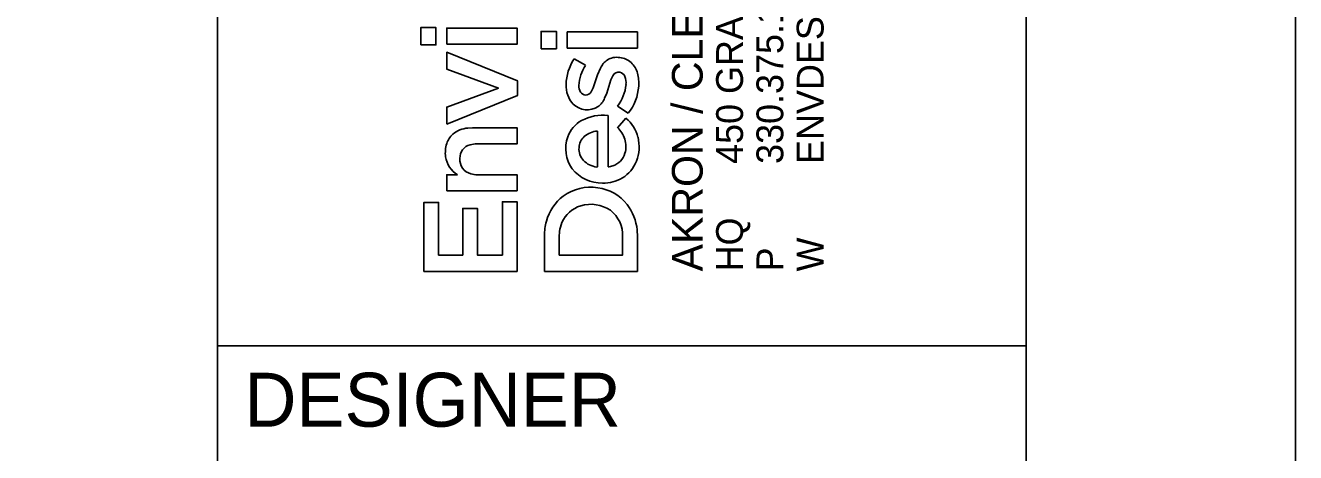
# Model space of a CAD drawing. Extents: x -0.2 to 34, y 0 to 22.
# Drawn here: x 31.644 to 34, y 2.302 to 3.094 of the extents above; entities that cross this region are included whole.
import ezdxf

# ---------------------------------------------------------------- set-up
doc = ezdxf.new("R2010")
doc.units = 0
for name, color, linetype in [('SH_Border', 7, 'Continuous'), ('SH_Cut_Line', 7, 'Continuous'), ('SH_Data', 7, 'Continuous')]:
    doc.layers.add(name, color=color, linetype=linetype)

msp = doc.modelspace()

# ---------------------------------------------------------------- linework, layer by layer
at = {"layer": 'SH_Border'}
for p, q in [((32, 0.5), (32, 21.5)), ((32, 2.5), (33.5, 2.5))]:
    msp.add_line(p, q, dxfattribs=at)
msp.add_lwpolyline([(1.5, 21.5), (33.5, 21.5), (33.5, 0.5), (1.5, 0.5)], close=True, dxfattribs=at)
at = {"layer": 'SH_Cut_Line'}
msp.add_lwpolyline([(0, 0), (34, 0), (34, 22), (0, 22)], close=True, dxfattribs=at)
at = {"layer": 'SH_Data'}
for p, q in [((32.3771, 3.0582), (32.3771, 3.0903)), ((32.3771, 3.0903), (32.4054, 3.0903)), ((32.4054, 3.0903), (32.4054, 3.0582)), ((32.4254, 3.0594), (32.4254, 3.0893)), ((32.4254, 3.0893), (32.5557, 3.0893)), ((32.5557, 3.0893), (32.5557, 3.0594)), ((32.6005, 3.0511), (32.6005, 3.0832)), ((32.6005, 3.0832), (32.6289, 3.0832)), ((32.6289, 3.0832), (32.6289, 3.0511)), ((32.6489, 3.0523), (32.6489, 3.0822)), ((32.6489, 3.0822), (32.7792, 3.0822)), ((32.7792, 3.0822), (32.7792, 3.0523)), ((32.4054, 3.0582), (32.3771, 3.0582)), ((32.5557, 3.0594), (32.4254, 3.0594)), ((32.4254, 3.0133), (32.4254, 3.0446)), ((32.4254, 3.0446), (32.5567, 2.9913)), ((32.6289, 3.0511), (32.6005, 3.0511)), ((32.7792, 3.0523), (32.6489, 3.0523)), ((32.6615, 3.0321), (32.6827, 3.0203)), ((32.5212, 2.978), (32.4254, 3.0133)), ((32.6967, 2.9787), (32.7048, 3.0026)), ((32.7048, 3.0026), (32.7104, 3.0153)), ((32.7298, 2.9933), (32.7221, 2.9688)), ((32.7334, 3.001), (32.7298, 2.9933)), ((32.4254, 2.9429), (32.5212, 2.978)), ((32.5567, 2.9913), (32.5567, 2.9644)), ((32.693, 2.9712), (32.6967, 2.9787)), ((32.5567, 2.9644), (32.4254, 2.9109)), ((32.7221, 2.9688), (32.7182, 2.9592)), ((32.4254, 2.9109), (32.4254, 2.9429)), ((32.7245, 2.9275), (32.7246, 2.8319)), ((32.7621, 2.9314), (32.742, 2.9447)), ((32.7423, 2.9046), (32.7577, 2.922)), ((32.4644, 2.904), (32.4729, 2.9044)), ((32.4729, 2.9044), (32.5557, 2.9044)), ((32.5557, 2.9044), (32.5557, 2.8746)), ((32.7049, 2.8318), (32.7049, 2.8983)), ((32.5557, 2.8746), (32.4814, 2.8746)), ((32.7036, 2.8317), (32.7049, 2.8318)), ((32.4254, 2.7875), (32.4254, 2.8173)), ((32.4254, 2.8173), (32.4455, 2.8173)), ((32.4822, 2.8173), (32.5557, 2.8173)), ((32.5557, 2.8173), (32.5557, 2.7876)), ((32.5557, 2.7876), (32.4254, 2.7875)), ((32.383, 2.6379), (32.383, 2.766)), ((32.383, 2.766), (32.4101, 2.766)), ((32.4101, 2.766), (32.4101, 2.6683)), ((32.5286, 2.6683), (32.5286, 2.7672)), ((32.5286, 2.7672), (32.5557, 2.7672)), ((32.5557, 2.7672), (32.5557, 2.6379)), ((32.455, 2.6683), (32.455, 2.7549)), ((32.455, 2.7549), (32.4822, 2.7549)), ((32.4822, 2.7549), (32.4822, 2.6683)), ((32.6347, 2.7118), (32.6341, 2.7023)), ((32.7785, 2.715), (32.7792, 2.7021)), ((32.6064, 2.638), (32.6064, 2.704)), ((32.6341, 2.7023), (32.6341, 2.6684)), ((32.7515, 2.6683), (32.7515, 2.7024)), ((32.7792, 2.7021), (32.7792, 2.638)), ((32.4101, 2.6683), (32.455, 2.6683)), ((32.4822, 2.6683), (32.5286, 2.6683)), ((32.6341, 2.6684), (32.7515, 2.6683)), ((32.5557, 2.6379), (32.383, 2.6379)), ((32.7792, 2.638), (32.6064, 2.638))]:
    msp.add_line(p, q, dxfattribs=at)
for points in [[(32.3771, 3.0582), (32.3771, 3.0903), (32.4054, 3.0903), (32.4054, 3.0582)], [(32.4254, 3.0594), (32.4254, 3.0893), (32.5557, 3.0893), (32.5557, 3.0594)], [(32.6005, 3.0511), (32.6005, 3.0832), (32.6289, 3.0832), (32.6289, 3.0511)], [(32.6489, 3.0523), (32.6489, 3.0822), (32.7792, 3.0822), (32.7792, 3.0523)], [(32.4254, 2.9109), (32.4254, 2.9429), (32.5212, 2.978), (32.4254, 3.0133), (32.4254, 3.0446), (32.5567, 2.9913), (32.5567, 2.9644)], [(32.383, 2.6379), (32.383, 2.766), (32.4101, 2.766), (32.4101, 2.6683), (32.455, 2.6683), (32.455, 2.7549), (32.4822, 2.7549), (32.4822, 2.6683), (32.5286, 2.6683), (32.5286, 2.7672), (32.5557, 2.7672), (32.5557, 2.6379)]]:
    msp.add_lwpolyline(points, close=True, dxfattribs=at)
for points in [[(32.6615, 3.0321), (32.6827, 3.0203)], [(32.693, 2.9712), (32.6967, 2.9787), (32.7048, 3.0026), (32.7104, 3.0153)], [(32.7334, 3.001), (32.7298, 2.9933), (32.7221, 2.9688), (32.7182, 2.9592)], [(32.7245, 2.9275), (32.7246, 2.8319)], [(32.7621, 2.9314), (32.742, 2.9447)], [(32.7423, 2.9046), (32.7577, 2.922)], [(32.4644, 2.904), (32.4729, 2.9044), (32.5557, 2.9044), (32.5557, 2.8746), (32.4814, 2.8746)], [(32.7036, 2.8317), (32.7049, 2.8318), (32.7049, 2.8983)], [(32.4254, 2.7875), (32.4254, 2.8173), (32.4455, 2.8173)], [(32.4822, 2.8173), (32.5557, 2.8173), (32.5557, 2.7876), (32.4254, 2.7875)], [(32.7785, 2.715), (32.7792, 2.7021), (32.7792, 2.638), (32.6064, 2.638)], [(32.6347, 2.7118), (32.6341, 2.7023), (32.6341, 2.6684), (32.7515, 2.6683), (32.7515, 2.7024)], [(32.6064, 2.638), (32.6064, 2.704)]]:
    msp.add_lwpolyline(points, dxfattribs=at)
for centre, radius, start, end in [((32.7364, 2.9826), 0.0897, 146.531, 178.7571), ((32.7364, 2.9826), 0.0897, 146.531, 178.7571), ((32.7452, 2.9789), 0.0749, 146.5112, 176.9101), ((32.7452, 2.9789), 0.0749, 146.5112, 176.9101), ((32.7466, 2.9971), 0.0405, 125.5118, 153.4159), ((32.7466, 2.9971), 0.0405, 125.5118, 153.4159), ((32.7406, 3.0026), 0.0326, 80.1719, 122.5197), ((32.7406, 3.0026), 0.0326, 80.1719, 122.5197), ((32.7428, 2.9982), 0.0367, 47.7934, 84.6892), ((32.7428, 2.9982), 0.0367, 47.7934, 84.6892), ((32.7379, 2.9946), 0.0427, 14.9966, 46.2063), ((32.7379, 2.9946), 0.0427, 14.9966, 46.2063), ((32.7438, 2.9963), 0.0114, 76.6609, 155.7053), ((32.7438, 2.9963), 0.0114, 76.6609, 155.7053), ((32.744, 2.9951), 0.0126, 21.5098, 78.5262), ((32.744, 2.9951), 0.0126, 21.5098, 78.5262), ((32.7259, 2.9877), 0.0321, 354.5726, 22.068), ((32.7259, 2.9877), 0.0321, 354.5726, 22.068), ((32.7104, 2.9867), 0.0712, 355.8306, 15.3914), ((32.7104, 2.9867), 0.0712, 355.8306, 15.3914), ((32.6967, 2.9824), 0.0501, 177.5366, 222.7932), ((32.6967, 2.9824), 0.0501, 177.5366, 222.7932), ((32.6931, 2.9823), 0.0228, 178.4747, 211.0868), ((32.6931, 2.9823), 0.0228, 178.4747, 211.0868), ((32.6833, 2.9767), 0.0115, 212.2368, 268.3777), ((32.6833, 2.9767), 0.0115, 212.2368, 268.3777), ((32.6834, 2.9759), 0.0107, 267.716, 333.7337), ((32.6834, 2.9759), 0.0107, 267.716, 333.7337), ((32.6825, 2.9915), 0.0757, 321.811, 354.7969), ((32.6825, 2.9915), 0.0757, 321.811, 354.7969), ((32.6895, 2.9882), 0.0922, 321.9777, 355.8738), ((32.6895, 2.9882), 0.0922, 321.9777, 355.8738), ((32.686, 2.9753), 0.0375, 225.9854, 302.4797), ((32.686, 2.9753), 0.0375, 225.9854, 302.4797), ((32.681, 2.9758), 0.0408, 308.0877, 335.9874), ((32.681, 2.9758), 0.0408, 308.0877, 335.9874), ((32.7152, 2.8441), 0.0838, 83.615, 118.2876), ((32.7152, 2.8441), 0.0838, 83.615, 118.2876), ((32.7174, 2.8717), 0.0644, 13.5336, 51.3615), ((32.7174, 2.8717), 0.0644, 13.5336, 51.3615), ((32.4687, 2.8543), 0.0499, 94.9696, 130.2225), ((32.4687, 2.8543), 0.0499, 94.9696, 130.2225), ((32.7024, 2.8691), 0.0558, 118.8308, 160.6244), ((32.7024, 2.8691), 0.0558, 118.8308, 160.6244), ((32.7079, 2.8561), 0.0424, 94.008, 130.8817), ((32.7079, 2.8561), 0.0424, 94.008, 130.8817), ((32.7038, 2.8656), 0.0549, 19.0357, 45.4406), ((32.7038, 2.8656), 0.0549, 19.0357, 45.4406), ((32.4787, 2.8582), 0.056, 162.2736, 187.7919), ((32.4787, 2.8582), 0.056, 162.2736, 187.7919), ((32.4635, 2.8626), 0.0402, 132.2219, 161.6818), ((32.4635, 2.8626), 0.0402, 132.2219, 161.6818), ((32.7104, 2.8661), 0.0644, 160.5201, 215.7831), ((32.7104, 2.8661), 0.0644, 160.5201, 215.7831), ((32.7005, 2.8663), 0.0298, 132.9851, 177.179), ((32.7005, 2.8663), 0.0298, 132.9851, 177.179), ((32.7107, 2.8697), 0.047, 344.6059, 17.007), ((32.7107, 2.8697), 0.047, 344.6059, 17.007), ((32.7064, 2.8692), 0.0758, 339.3542, 13.3785), ((32.7064, 2.8692), 0.0758, 339.3542, 13.3785), ((32.4748, 2.8487), 0.025, 103.6865, 182.2187), ((32.4748, 2.8487), 0.025, 103.6865, 182.2187), ((32.4811, 2.8286), 0.046, 89.6049, 105.3284), ((32.4811, 2.8286), 0.046, 89.6049, 105.3284), ((32.7017, 2.865), 0.0311, 175.0013, 223.283), ((32.7017, 2.865), 0.0311, 175.0013, 223.283), ((32.7224, 2.8671), 0.035, 288.0077, 343.5508), ((32.7224, 2.8671), 0.035, 288.0077, 343.5508), ((32.4703, 2.858), 0.0476, 188.962, 238.7037), ((32.4703, 2.858), 0.0476, 188.962, 238.7037), ((32.4773, 2.8456), 0.0276, 175.5854, 255.1439), ((32.4773, 2.8456), 0.0276, 175.5854, 255.1439), ((32.7125, 2.8705), 0.0687, 217.7452, 271.6543), ((32.7125, 2.8705), 0.0687, 217.7452, 271.6543), ((32.7089, 2.8736), 0.0423, 225.0619, 262.7974), ((32.7089, 2.8736), 0.0423, 225.0619, 262.7974), ((32.7247, 2.8522), 0.0202, 269.7003, 294.8711), ((32.7247, 2.8522), 0.0202, 269.7003, 294.8711), ((32.7189, 2.8652), 0.0626, 300.9427, 338.7323), ((32.7189, 2.8652), 0.0626, 300.9427, 338.7323), ((32.4818, 2.8595), 0.0422, 254.0916, 270.5284), ((32.4818, 2.8595), 0.0422, 254.0916, 270.5284), ((32.7155, 2.8724), 0.0706, 269.2048, 300.3341), ((32.7155, 2.8724), 0.0706, 269.2048, 300.3341), ((32.6923, 2.7079), 0.0864, 81.194, 125.9984), ((32.6923, 2.7079), 0.0864, 81.194, 125.9984), ((32.6946, 2.7113), 0.0827, 37.8521, 82.402), ((32.6946, 2.7113), 0.0827, 37.8521, 82.402), ((32.6939, 2.7089), 0.0865, 127.2362, 165.148), ((32.6939, 2.7089), 0.0865, 127.2362, 165.148), ((32.6889, 2.7078), 0.054, 106.1881, 157.3861), ((32.6889, 2.7078), 0.054, 106.1881, 157.3861), ((32.6928, 2.6986), 0.0639, 55.6727, 107.2093), ((32.6928, 2.6986), 0.0639, 55.6727, 107.2093), ((32.6859, 2.7057), 0.0931, 5.7333, 37.304), ((32.6859, 2.7057), 0.0931, 5.7333, 37.304), ((32.6929, 2.705), 0.0587, 357.4662, 52.2665), ((32.6929, 2.705), 0.0587, 357.4662, 52.2665), ((32.7143, 2.7028), 0.1078, 164.7861, 179.3704), ((32.7143, 2.7028), 0.1078, 164.7861, 179.3704), ((32.6983, 2.7039), 0.0641, 157.3571, 172.9275), ((32.6983, 2.7039), 0.0641, 157.3571, 172.9275)]:
    msp.add_arc(centre, radius, start, end, dxfattribs=at)

# ---------------------------------------------------------------- texts
for s, height, p in [('450 GRANT ST., AKRON, OH  44311', 0.049846, (32.9749, 2.8374)), ('AKRON / CLEVELAND / COLUMBUS', 0.056969, (32.9001, 2.638)), ('ENVDESIGNGROUP.COM', 0.049846, (33.1244, 2.8374)), ('330.375.1390', 0.049846, (33.0497, 2.8374)), ('HQ ', 0.04985, (32.9749, 2.638)), ('W', 0.0498, (33.1244, 2.638)), ('P', 0.0498, (33.0497, 2.638))]:
    msp.add_text(s, height=height, rotation=90, dxfattribs=at).set_placement(p)
msp.add_text('DESIGNER', height=0.1, dxfattribs=at).set_placement((32.05, 2.35))

doc.saveas('drawing.dxf')
